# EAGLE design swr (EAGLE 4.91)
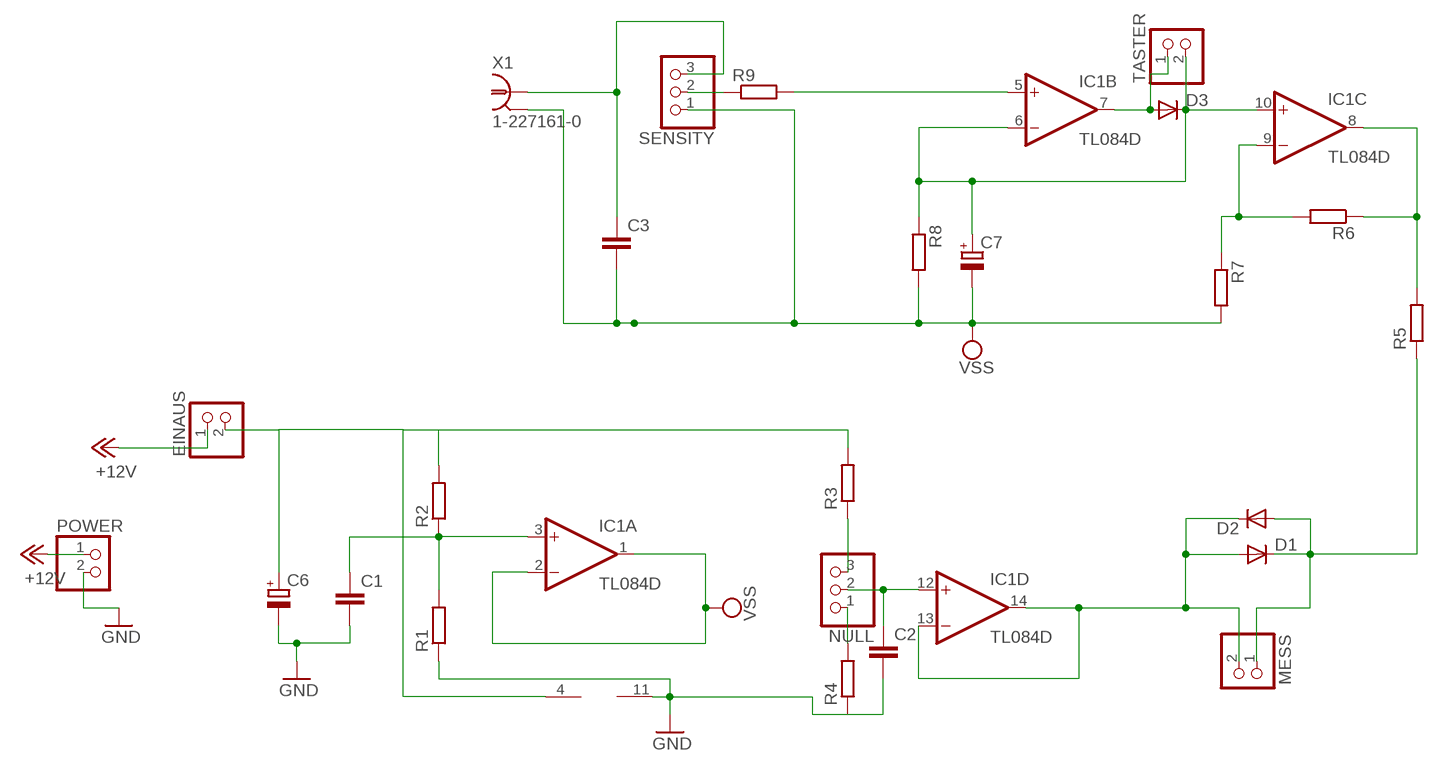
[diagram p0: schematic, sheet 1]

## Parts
C1  C-EUC0805  [C0805]
C2  C-EUC0805  [C0805]
C3  C-EUC0805  [C0805]
C6  CPOL-EUSMCD  [SMC_D]
C7  CPOL-EUSMCD  [SMC_D]
D1  DIODE-SOD123  [SOD123]
D2  DIODE-SOD123  [SOD123]
D3  DIODE-SOD123  [SOD123]
EINAUS  PINHD-1X2_2.54  [1X02]
IC1  TL084D  [SO14]
MESS  PINHD-1X2_2.54  [1X02]
NULL  PINHD-1X3_2.54  [1X03]
POWER  PINHD-1X2_2.54  [1X02]
R1  R-EU_R0805  [R0805]
R2  R-EU_R0805  [R0805]
R3  R-EU_R0805  [R0805]
R4  R-EU_R0805  [R0805]
R5  R-EU_R0805  [R0805]
R6  R-EU_R0805  [R0805]
R7  R-EU_R0805  [R0805]
R8  R-EU_R0805  [R0805]
R9  R-EU_R0805  [R0805]
SENSITY  PINHD-1X3_2.54  [1X03]
TASTER  PINHD-1X2_2.54  [1X02]
X1  1-227161-0  [AMP_227161]

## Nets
+12V: EINAUS.1 POWER.1
GND: C1.2 C2.2 C6.- IC1.11(P:V-) POWER.2 R1.1 R4.1
N$1: C6.+ EINAUS.2 IC1.4(P:V+) R2.2 R3.2
N$2: IC1.8(C:OUT) R5.2 R6.1
N$3: IC1.9(C:-IN) R6.2 R7.1
N$4: D1.C D2.A MESS.1 R5.1
N$5: C7.+ D3.C IC1.6(B:-IN) IC1.10(C:+IN) R8.1 TASTER.2
N$6: IC1.5(B:+IN) R9.2
N$7: C1.1 IC1.3(A:+IN) R1.2 R2.1
N$9: D1.A D2.C IC1.13(D:-IN) IC1.14(D:OUT) MESS.2
N$10: C2.1 IC1.12(D:+IN) NULL.2
N$12: NULL.1 R4.2
N$13: NULL.3 R3.1
N$14: R9.1 SENSITY.2
N$15: C3.1 SENSITY.3 X1.1
N$17: D3.A IC1.7(B:OUT) TASTER.1
VSS: C3.2 C7.- IC1.1(A:OUT) IC1.2(A:-IN) R7.2 R8.2 SENSITY.1 X1.2(GND)

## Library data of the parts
C1-C3 = rcl:C-EU: CAPACITOR, European symbol
C6 C7 = rcl:CPOL-EU: POLARIZED CAPACITOR, European symbol
D1-D3 = diode:DIODE-: DIODE
EINAUS MESS POWER TASTER = pinhead:PINHD-1X2: PIN HEADER
IC1 = linear:TL084: OP AMP
NULL SENSITY = pinhead:PINHD-1X3: PIN HEADER
R1-R9 = rcl:R-EU_: RESISTOR, European symbol
X1 = con-coax:?227161*: JACK, RIGHT ANGLE, 50 OHM, PCB, BNC

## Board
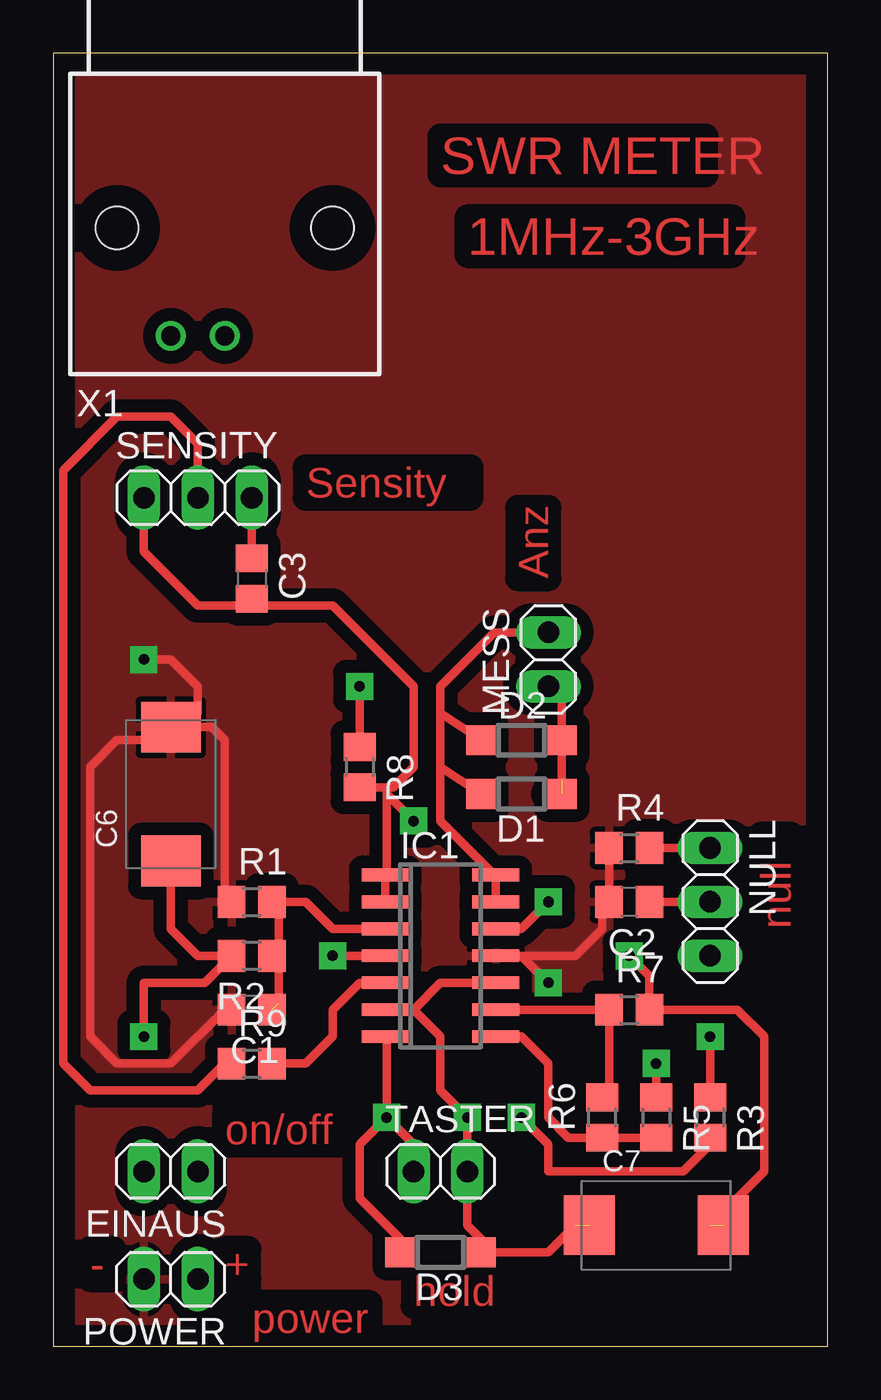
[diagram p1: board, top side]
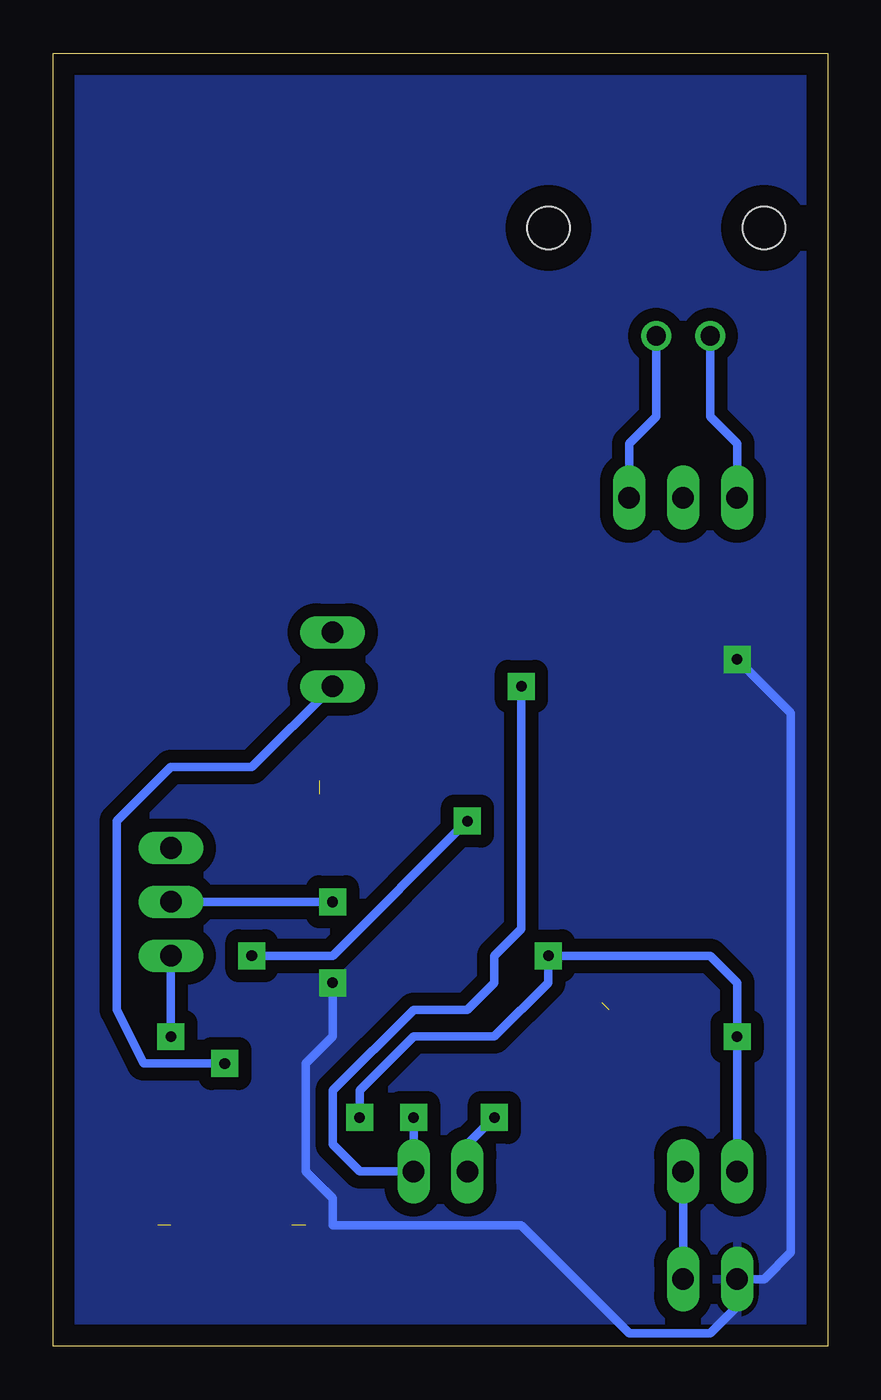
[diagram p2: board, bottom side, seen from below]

Size 36.5 x 60.95 mm. Coordinates in mm from the lower left corner, seen from the top.
Outline: 0,0 36.5,0 36.5,60.95 0,60.95 0,0
Copper layers (1*16): Top 0.035mm / dielectric 1.5mm / Bottom 0.035mm
Design rules "default": minimum track width 10mil, minimum drill 24mil, track to track 8mil, track to pad 8mil, pad to pad 8mil, via to via 8mil, smd to smd 8mil, copper to edge 40mil, drill to drill 8mil, minimum pad ring 10mil, minimum via ring 8mil, stop-mask expansion 4mil, vias tented up to drill 0mil, thermal gap 10mil

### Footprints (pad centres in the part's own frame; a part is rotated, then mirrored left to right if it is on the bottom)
C0805 = smd 1.3 x 1.5: 1 -0.95,0; 2 0.95,0
SMC_D = smd 2.4 x 2.8: + -3.15,0; - 3.15,0
SOD123 = smd 1.4 x 1.4: A 1.9,0; C -1.9,0
1X02 = drill 1.016 long: 1 -1.27,0; 2 1.27,0
SO14 = smd 0.6 x 2.2: 1 -3.81,-2.6; 2 -2.54,-2.6; 3 -1.27,-2.6; 4 0,-2.6; 5 1.27,-2.6; 6 2.54,-2.6; 7 3.81,-2.6; 8 3.81,2.6; 9 2.54,2.6; 10 1.27,2.6; 11 0,2.6; 12 -1.27,2.6; 13 -2.54,2.6; 14 -3.81,2.6
1X03 = drill 1.016 long: 1 -2.54,0; 2 0,0; 3 2.54,0
R0805 = smd 1.3 x 1.5: 1 -0.95,0; 2 0.95,0
AMP_227161 = drill 0.9 pad 1.27 round: 1 0,-5.08; 2 -2.54,-5.08 | hole 2: -5.08,0; 5.08,0

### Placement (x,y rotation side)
C1  9.36,15.87 180 top
C2  27.14,20.95 180 top
C3  9.36,36.19 270 top
C6  5.55,26.03 90 top
C7  28.41,5.71 0 top
D1  22.06,26.03 180 top
D2  22.06,28.57 0 top
D3  18.25,4.44 180 top
EINAUS  5.55,8.25 180 top
IC1  18.25,18.41 270 top
MESS  23.33,32.38 90 top
NULL  30.95,20.95 270 top
POWER  5.55,3.17 180 top
R1  9.36,20.95 0 top
R2  9.36,18.41 180 top
R3  30.95,10.79 270 top
R4  27.14,23.49 0 top
R5  28.41,10.79 270 top
R6  25.87,10.79 90 top
R7  27.14,15.87 0 top
R8  14.44,27.3 270 top
R9  9.36,13.33 0 top
SENSITY  6.82,40 0 top
TASTER  18.25,8.25 0 top
X1  8.09,52.7 0 top

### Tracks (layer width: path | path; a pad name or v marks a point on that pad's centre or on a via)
+12V
  Bottom 0.406: POWER.1 EINAUS.1
GND  (via drill 0.5 pad 1.27)
  Top 0.406: C6.- 7.48,29.18 8.09,28.57 8.09,20.95 R1.1 | C1.2 8.09,15.87 5.55,13.33 3.01,13.33 1.74,14.6 1.74,27.3 3.01,28.57 5.55,28.57 6.82,29.84 6.82,31.11 5.55,32.38 v4.28,32.38 | R4.1 25.87,23.49 26.19,23.17 C2.2 25.87,20.95 25.87,19.68 24.6,18.41 IC1.11 22.06,18.41 v23.33,17.14
  Bottom 0.406: v23.33,17.14 23.33,14.6 24.6,13.33 24.6,8.25 23.33,6.98 23.33,5.71 14.44,5.71 9.36,0.63 5.55,0.63 4.28,1.9 POWER.2 3.01,3.17 1.74,4.44 1.74,29.84 v4.28,32.38
  pour Top (isolate 0.61): 0.47,60.32 36.03,60.32 36.03,-0.64 0.47,-0.64 0.47,57.78
  pour Bottom (isolate 0.61): 0.47,61.59 37.3,61.59 37.3,-0.64 -0.8,-0.64 -0.8,57.78
N$1  (via drill 0.5 pad 1.27)
  Top 0.406: v4.28,14.6 4.28,17.14 7.14,17.14 R2.2 6.82,18.41 5.55,19.68 C6.+ | v13.17,18.41 IC1.4 | v22.06,10.79 23.33,9.52 23.33,8.25 29.68,8.25 30.95,9.52 R3.2
  Bottom 0.406: EINAUS.2 v4.28,14.6 4.28,17.14 5.55,18.41 v13.17,18.41 13.17,17.14 15.71,14.6 19.52,14.6 22.06,12.06 v22.06,10.79
N$2
  Top 0.406: 20.79,14.6 IC1.8 22.06,14.6 23.33,13.33 23.33,10.79 24.28,9.84 R6.1 25.87,9.52 26.19,9.84 R5.2
N$3
  Top 0.406: IC1.9 R7.1 26.19,12.38 25.87,12.06 R6.2
N$4  (via drill 0.5 pad 1.27)  (1 unrouted)
  Top 0.406: MESS.1 23.96,30.48 D2.A 23.96,26.66 23.33,26.03 | R5.1 v28.41,13.33
  Bottom 0.406: v28.41,13.33 32.22,13.33 33.49,15.87 33.49,24.76 30.95,27.3 27.14,27.3 MESS.1
N$5  (via drill 0.5 pad 1.27)  (1 unrouted)
  Top 0.406: 14.44,28.57 R8.1 v14.44,31.11 | 16.98,15.87 IC1.6 | 16.98,15.87 18.25,17.14 IC1.10 | 16.98,15.87 18.25,14.6 18.25,12.06 v19.52,10.79 TASTER.2 19.52,5.71 20.79,4.44 | D3.C 20.79,4.44 | 20.79,4.44 23.33,4.44 24.6,5.71
  Bottom 0.406: v19.52,10.79 TASTER.2 22.06,8.25 23.33,9.52 23.33,12.06 19.52,15.87 16.98,15.87 15.71,17.14 15.71,18.41 14.44,19.68 v14.44,31.11
N$6
  Top 0.406: IC1.5 14.44,17.14 13.17,15.87 13.17,14.6 11.9,13.33 R9.2
N$7  (1 unrouted)
  Top 0.406: 15.71,19.68 IC1.3 13.17,19.68 11.9,20.95 R1.2 10.63,20.63 10.63,18.41 | R2.1 10.63,18.41 | 10.63,18.41 10.63,16.19
N$9
  Top 0.406: IC1.13 20.85,22.16 20.79,22.22 | 20.79,22.22 IC1.14 | 20.79,22.22 18.25,24.76 18.25,27.3 | 18.25,27.3 18.25,29.84 | 18.25,29.84 18.25,31.11 20.79,33.65 MESS.2 | 18.25,27.3 D1.A | 18.25,29.84 D2.C
N$10  (via drill 0.5 pad 1.27)
  Top 0.406: NULL.2 C2.1 | IC1.12 22.06,19.68 v23.33,20.95
  Bottom 0.406: v23.33,20.95 NULL.2
N$12
  Top 0.406: R4.2 NULL.1
N$13  (via drill 0.5 pad 1.27)
  Top 0.406: R3.1 v30.95,14.6
  Bottom 0.406: v30.95,14.6 NULL.3
N$14
  Top 0.406: R9.1 8.09,13.33 6.82,12.06 1.74,12.06 0.47,13.33 0.47,41.27 3.01,43.81 5.55,43.81 6.82,42.54 SENSITY.2
N$15
  Top 0.406: C3.1 SENSITY.3
  Bottom 0.406: X1.1 8.09,43.81 9.36,42.54 SENSITY.3
N$17  (via drill 0.5 pad 1.27)
  Top 0.406: IC1.7 15.71,14.6 v15.71,10.79 | D3.A 16.35,5.07 14.44,6.98 14.44,9.52 v15.71,10.79 | v15.71,10.79 16.98,9.52 TASTER.1
  Bottom 0.406: TASTER.1 16.98,9.52 v15.71,10.79
VSS  (via drill 0.5 pad 1.27)  (1 unrouted)
  Top 0.406: 15.71,22.22 IC1.1 | SENSITY.1 4.28,37.46 6.82,34.92 9.36,34.92 | 15.71,26.35 R8.2 | 15.71,26.35 16.03,26.35 16.98,27.3 16.98,31.11 13.17,34.92 9.36,34.92 | 9.36,34.92 C3.2 | IC1.2 15.65,22.16 15.71,22.22 | 15.71,22.22 15.71,26.03 | 15.71,26.03 15.71,26.35 | 30.95,5.71 33.49,8.25 33.49,14.6 32.22,15.87 R7.2 28.09,17.46 v27.14,18.41 | 15.71,26.03 v16.98,24.76
  Bottom 0.406: X1.2 5.55,43.81 4.28,42.54 SENSITY.1 | v27.14,18.41 23.33,18.41 v16.98,24.76

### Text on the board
Top: SWR METER | 1MHz-3GHz | Sensity | Anz | null | on/off | - | + | hold | power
